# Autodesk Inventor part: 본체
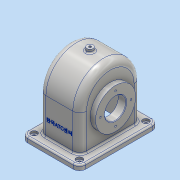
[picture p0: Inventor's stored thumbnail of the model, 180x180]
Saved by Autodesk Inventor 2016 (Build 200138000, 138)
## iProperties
Created: 2018-11
Part Number: 본체
Material: 알루미늄 6061
Document SubType Name: Modeling
Designer: user
Density: 2.7 g/cm^3
Appearance: 알루미늄 - 평지
Mass: 1090.76 g
Surface Area: 1185.12 cm^2
Volume: 403.984 cm^3
Author: user
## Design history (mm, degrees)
sketch "스케치1"
  geometry: L1 (-55, -75)-(55, -75); L2 (55, -75)-(55, 75); L3 (55, 75)-(-55, 75); L4 (-55, 75)-(-55, -75); L5 (-55, -75)-(55, 75); L6 (55, -75)-(-55, 75); 1 further point
  constraints: 12 end point, 2 midpoint, 2 parallel, 1 horizontal, 1 perpendicular
  dimensions: "d0" = 110 distance of L3.end L2.end; "d1" = 150 distance of L2.end L1.end
extrude "돌출1" new body sketch "스케치1" distance "d2" = 10; taper "d3" = 0 deg
sketch "스케치2"
  geometry: L1 (-38.5, 58)-(38.5, 58); L2 (38.5, 58)-(38.5, -58); L3 (38.5, -58)-(-38.5, -58); L4 (-38.5, -58)-(-38.5, 58); L5 (-38.5, 58)-(38.5, -58); L6 (38.5, 58)-(-38.5, -58); 1 further point
  constraints: 12 end point, 2 midpoint, 2 parallel, 1 horizontal, 1 perpendicular
  dimensions: "d4" = 77 distance of L2.end L3.end; "d5" = 116 distance of L1.end L2.end
extrude "돌출2" join sketch "스케치2" distance "d6" = 126; taper "d7" = 0 deg
fillet "모깎기1" dims "d8" = 58
feature "쉘1" dims "d11" = 6, "d12" = 10, "d13" = 5
sketch "스케치4"
  geometry: L1 (-10, 133)-(-10, -17) reference; C1 r 38 at (55, 58); 2 further points
  constraints: 1 centre point, 1 horizontal alignment, 1 midpoint
  dimensions: "d14" = 76 diameter of C1; "d15" = 65 distance from line of L1 C1.centre
extrude "돌출3" join sketch "스케치4" distance "d16" = 5; taper "d18" = 0 deg; dims "d17" = 0, "d19" = 0
sketch "스케치6"
  geometry: L1 (-65, 75)-(-65, -75) reference; C1 r 20 at (0, 0); 2 further points
  constraints: 1 centre point, 1 horizontal alignment, 1 midpoint
  dimensions: "d21" = 40 diameter of C1; "d22" = 65 distance from line of L1 C1.centre
extrude "돌출4" cut sketch "스케치6" distance "d23" = 24; taper "d24" = 0 deg
sketch "스케치7"
  geometry: L1 (10, -17)-(10, 133) reference; C1 r 38 at (-55, 58); 2 further points
  constraints: 1 centre point, 1 horizontal alignment, 1 midpoint
  dimensions: "d25" = 76 diameter of C1; "d26" = 65 distance from line of L1 C1.centre
extrude "돌출5" join sketch "스케치7" distance "d27" = 10; taper "d28" = 0 deg
sketch "스케치8"
  geometry: L1 (65, -75)-(65, 75) reference; C1 r 20 at (0, 0); 1 further point
  constraints: 1 centre point, 1 horizontal alignment
  dimensions: "d29" = 40 diameter of C1; "d30" = 65 distance from line of L1 C1.centre
extrude "돌출6" cut sketch "스케치8" distance "d31" = 15; taper "d32" = 0 deg
fillet "모깎기2" dims "d33" = 12
sketch "스케치10"
  geometry: L1 (65, -63)-(65, 63) reference; C1 r 38 at (0, 0) reference; 3 further points
  constraints: 1 horizontal alignment, 1 midpoint
  dimensions: "d42" = 29 distance of C1.centre point (-29, 0)
hole "구멍2" sketch "스케치10" at (-29, 0) diameter "d43" = 3.242; stored, may be unused: countersink angle "d47" = 90 deg, drill point angle "d49" = 118 deg; dims "d44" = 8, "d45" = 4, "d46" = 2, "d48" = 10
fillet "모깎기3" dims "d67" = 13
fillet "모깎기4" dims "d68" = 3
fillet "모깎기5" dims "d69" = 8
fillet "모깎기7" dims "d71" = 3
sketch "스케치15"
  geometry: C1 r 20 at (13, 0) reference; C2 r 20 at (13, 0) reference; C3 r 28 at (13, 0); 1 further point
  constraints: 1 centre point, 1 coincident
  dimensions: "d73" = 56 diameter of C3
extrude "돌출8" join sketch "스케치15" distance "d74" = 14; taper "d75" = 0 deg
feature "면 기울기3" dims angle "d76" = 40 deg
sketch "스케치16"
  geometry: C1 r 20 at (0, 0) reference; 1 further point
extrude "돌출9" cut sketch "스케치16" stored distance "d77" = 14; taper "d78" = 0 deg
node "작업 평면2"
sketch "스케치17"
  geometry: C1 r 6 at (0, 0); 1 further point
  constraints: 1 centre point, 1 coincident
  dimensions: "d82" = 12 diameter of C1
extrude "돌출10" join sketch "스케치17" stored distance "d83" = 14; taper "d84" = 5 deg
sketch "스케치18"
  geometry: 2 further points
  constraints: 1 coincident
hole "구멍4" sketch "스케치18" at (0, 0) diameter "d85" = 4.459; stored, may be unused: countersink angle "d89" = 90 deg, drill point angle "d91" = 118 deg; dims "d86" = 12, "d87" = 4, "d88" = 2, "d90" = 12
fillet "모깎기8" dims "d92" = 3
chamfer "모따기1" distance "d93" = 1; stored, may be unused: second distance "d94" = 2, angle "d95" = 45 deg
sketch "스케치19"
  geometry: L1 (-17.5, -78)-(68.5, -78) reference; L2 (-13, 0)-(-13, -65) reference; 2 further points
  constraints: 1 midpoint, 1 vertical alignment, 1 other
  dimensions: "d96" = 40 distance from line of L1 point (25.5, -38); "d119" = 38.5 distance from line of L2 point (25.5, -38) (derived)
feature "엠보싱2" sketch "스케치19" dims "d97" = 0.5, "d98" = 0
sketch "스케치20"
  geometry: 1 further point
sketch "스케치21"
  geometry: L1 (-65, 63)-(-65, -63) reference; C1 r 38 at (0, 0) reference; 3 further points
  constraints: 1 horizontal alignment, 1 midpoint
  dimensions: "d100" = 29 distance of C1.centre point (29, 0)
hole "구멍5" sketch "스케치21" at (29, 0) diameter "d101" = 3.242; stored, may be unused: countersink angle "d105" = 90 deg, drill point angle "d107" = 118 deg; dims "d102" = 8, "d103" = 4, "d104" = 2, "d106" = 10
sketch "스케치22"
  geometry: 1 further point
sketch "스케치23"
  geometry: C1 r 6 at (-43, -63); A1 r 12 centre (-43, -63) between (-55, -63) and (-43, -75) reference; 1 further point
  constraints: 1 centre point, 1 coincident
  dimensions: "d111" = 12 diameter of C1
extrude "돌출11" cut sketch "스케치23" distance "d112" = 4; taper "d113" = 0 deg
sketch "스케치24"
  geometry: L1 (0, -12)-(86, -12) reference; L2 (-12, 126)-(-12, 0) reference; C1 r 2.5 at (0, 0); 1 further point
  constraints: 1 centre point
  dimensions: "d114" = 5 diameter of C1; "d115" = 12 distance from line of L1 C1.centre; "d116" = 12 distance from line of L2 C1.centre
extrude "돌출12" cut sketch "스케치24" distance "d117" = 10; taper "d118" = 0 deg
fillet "모깎기9" dims "d120" = 3
node "솔리드1"
pattern_circular "원형 패턴1" dims angle "d51" = 360 deg
pattern_circular "원형 패턴2" dims angle "d109" = 360 deg
mirror "대칭4"
mirror "대칭5"
other parameters: "d81" = 142
